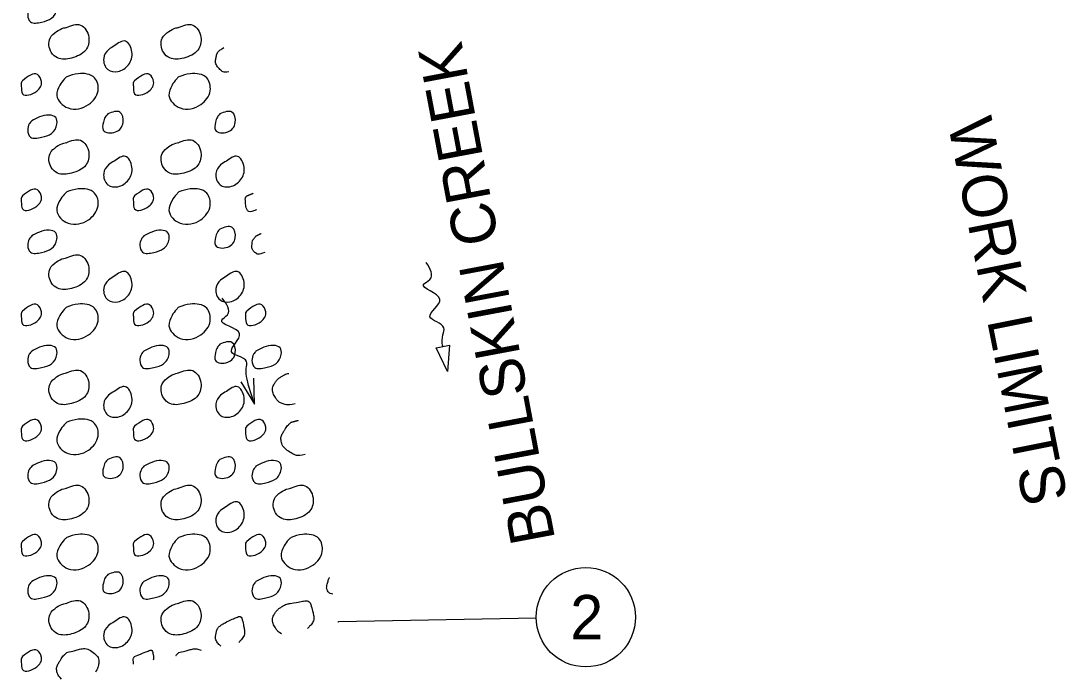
# Model space of a CAD drawing. Extents: x 0 to 340, y 0 to 220.
# Drawn here: x 150.51 to 183.47, y 110.25 to 131 of the extents above; entities that cross this region are included whole.
import ezdxf

# ---------------------------------------------------------------- set-up
doc = ezdxf.new("R2010")
doc.units = 0
for name, color, linetype in [('GE_P_Alignment_100_Stations', 7, 'Continuous'), ('MT_P_Temp_Road', 7, 'Continuous'), ('MT_P_Work_Area', 7, 'Continuous'), ('PF_P_Grade_Line', 7, 'Continuous'), ('SC_Scratch1', 7, 'Continuous'), ('TX_P_1', 7, 'Continuous')]:
    doc.layers.add(name, color=color, linetype=linetype)

msp = doc.modelspace()

# ---------------------------------------------------------------- linework, layer by layer
at = {"layer": 'GE_P_Alignment_100_Stations'}
msp.add_line((166.758, 112.174), (160.528, 112.053), dxfattribs=at)
at = {"layer": 'MT_P_Work_Area'}
msp.add_circle((168.325, 112.204), 1.567, dxfattribs=at)
at = {"layer": 'PF_P_Grade_Line'}
for p, q in [((157.884, 118.916), (157.856, 119.744)), ((157.446, 119.618), (157.884, 118.916))]:
    msp.add_line(p, q, dxfattribs=at)
msp.add_spline([(157.884, 118.916), (157.644, 119.711), (157.619, 120.048), (157.628, 120.268), (157.152, 120.566), (157.405, 121.151), (156.846, 121.565), (157.027, 121.739), (156.86, 122.263)], degree=3, dxfattribs=at)
at = {"layer": 'SC_Scratch1'}
for points in [[(150.855, 131.482), (151.105, 131.607), (151.405, 131.665), (151.616, 131.584), (151.65, 131.38), (151.48, 131.084), (151.166, 130.964), (150.815, 130.97), (150.729, 131.185), (150.78, 131.385), (150.855, 131.482)], [(151.941, 130.793), (152.395, 130.869), (152.655, 130.489), (152.558, 130.082), (152.112, 129.83), (151.672, 129.832), (151.473, 130.01), (151.436, 130.455), (151.641, 130.669), (151.867, 130.777), (151.95, 130.795)], [(155.477, 130.793), (155.931, 130.869), (156.19, 130.489), (156.094, 130.082), (155.648, 129.83), (155.208, 129.832), (155.009, 130.01), (154.972, 130.455), (155.177, 130.669), (155.403, 130.777), (155.485, 130.795)], [(153.457, 130.21), (153.809, 130.361), (154.016, 130.023), (153.905, 129.618), (153.571, 129.405), (153.26, 129.465), (153.127, 129.824), (153.273, 130.091), (153.457, 130.21)], [(150.563, 129.115), (151.038, 129.308), (151.164, 129.09), (151.015, 128.787), (150.565, 128.703), (150.525, 128.943), (150.53, 129.064), (150.563, 129.115)], [(151.962, 129.241), (152.318, 129.335), (152.839, 129.203), (152.946, 128.8), (152.65, 128.365), (152.002, 128.255), (151.648, 128.653), (151.743, 128.971), (151.881, 129.164), (151.962, 129.241)], [(154.099, 129.115), (154.574, 129.308), (154.699, 129.09), (154.55, 128.787), (154.1, 128.703), (154.061, 128.943), (154.065, 129.064), (154.099, 129.115)], [(155.498, 129.241), (155.854, 129.335), (156.374, 129.203), (156.482, 128.8), (156.186, 128.365), (155.538, 128.255), (155.184, 128.653), (155.279, 128.971), (155.417, 129.164), (155.498, 129.241)], [(150.855, 127.852), (151.105, 127.977), (151.405, 128.034), (151.616, 127.953), (151.65, 127.75), (151.48, 127.453), (151.166, 127.333), (150.815, 127.339), (150.729, 127.555), (150.78, 127.755), (150.855, 127.852)], [(153.253, 128.068), (153.635, 128.124), (153.739, 127.796), (153.499, 127.502), (153.112, 127.558), (153.115, 127.804), (153.173, 127.967), (153.253, 128.068)], [(156.789, 128.068), (157.17, 128.124), (157.274, 127.796), (157.034, 127.502), (156.648, 127.558), (156.65, 127.804), (156.709, 127.967), (156.789, 128.068)], [(151.941, 127.162), (152.395, 127.238), (152.655, 126.858), (152.558, 126.452), (152.112, 126.199), (151.672, 126.202), (151.473, 126.38), (151.436, 126.825), (151.641, 127.038), (151.867, 127.147), (151.95, 127.164)], [(155.477, 127.162), (155.931, 127.238), (156.19, 126.858), (156.094, 126.452), (155.648, 126.199), (155.208, 126.202), (155.009, 126.38), (154.972, 126.825), (155.177, 127.038), (155.403, 127.147), (155.485, 127.164)], [(153.457, 126.58), (153.809, 126.731), (154.016, 126.392), (153.905, 125.987), (153.571, 125.775), (153.26, 125.834), (153.127, 126.193), (153.273, 126.461), (153.457, 126.58)], [(156.993, 126.58), (157.344, 126.731), (157.552, 126.392), (157.44, 125.987), (157.107, 125.775), (156.796, 125.834), (156.663, 126.193), (156.809, 126.461), (156.993, 126.58)], [(150.563, 125.485), (151.038, 125.677), (151.164, 125.459), (151.015, 125.157), (150.565, 125.072), (150.525, 125.312), (150.53, 125.433), (150.563, 125.485)], [(151.962, 125.611), (152.318, 125.704), (152.839, 125.572), (152.946, 125.17), (152.65, 124.735), (152.002, 124.624), (151.648, 125.022), (151.743, 125.341), (151.881, 125.533), (151.962, 125.611)], [(154.099, 125.485), (154.574, 125.677), (154.699, 125.459), (154.55, 125.157), (154.1, 125.072), (154.061, 125.312), (154.065, 125.433), (154.099, 125.485)], [(155.498, 125.611), (155.854, 125.704), (156.374, 125.572), (156.482, 125.17), (156.186, 124.735), (155.538, 124.624), (155.184, 125.022), (155.279, 125.341), (155.417, 125.533), (155.498, 125.611)], [(150.855, 124.221), (151.105, 124.346), (151.405, 124.404), (151.616, 124.323), (151.65, 124.12), (151.48, 123.823), (151.166, 123.703), (150.815, 123.709), (150.729, 123.925), (150.78, 124.125), (150.855, 124.221)], [(154.39, 124.221), (154.64, 124.346), (154.941, 124.404), (155.152, 124.323), (155.186, 124.12), (155.015, 123.823), (154.702, 123.703), (154.35, 123.709), (154.264, 123.925), (154.316, 124.125), (154.39, 124.221)], [(156.789, 124.438), (157.17, 124.494), (157.274, 124.165), (157.034, 123.871), (156.648, 123.928), (156.65, 124.174), (156.709, 124.337), (156.789, 124.438)], [(151.941, 123.532), (152.395, 123.608), (152.655, 123.228), (152.558, 122.821), (152.112, 122.569), (151.672, 122.571), (151.473, 122.75), (151.436, 123.195), (151.641, 123.408), (151.867, 123.516), (151.95, 123.534)], [(153.457, 122.95), (153.809, 123.1), (154.016, 122.762), (153.905, 122.357), (153.571, 122.145), (153.26, 122.204), (153.127, 122.563), (153.273, 122.83), (153.457, 122.95)], [(156.993, 122.95), (157.344, 123.1), (157.552, 122.762), (157.44, 122.357), (157.107, 122.145), (156.796, 122.204), (156.663, 122.563), (156.809, 122.83), (156.993, 122.95)], [(150.563, 121.855), (151.038, 122.047), (151.164, 121.829), (151.015, 121.526), (150.565, 121.442), (150.525, 121.682), (150.53, 121.803), (150.563, 121.855)], [(151.962, 121.98), (152.318, 122.074), (152.839, 121.942), (152.946, 121.54), (152.65, 121.105), (152.002, 120.994), (151.648, 121.392), (151.743, 121.71), (151.881, 121.903), (151.962, 121.98)], [(154.099, 121.855), (154.574, 122.047), (154.699, 121.829), (154.55, 121.526), (154.1, 121.442), (154.061, 121.682), (154.065, 121.803), (154.099, 121.855)], [(155.498, 121.98), (155.854, 122.074), (156.374, 121.942), (156.482, 121.54), (156.186, 121.105), (155.538, 120.994), (155.184, 121.392), (155.279, 121.71), (155.417, 121.903), (155.498, 121.98)], [(157.634, 121.855), (158.109, 122.047), (158.235, 121.829), (158.086, 121.526), (157.636, 121.442), (157.597, 121.682), (157.601, 121.803), (157.634, 121.855)], [(150.855, 120.591), (151.105, 120.716), (151.405, 120.773), (151.616, 120.692), (151.65, 120.489), (151.48, 120.192), (151.166, 120.072), (150.815, 120.078), (150.729, 120.294), (150.78, 120.494), (150.855, 120.591)], [(154.39, 120.591), (154.64, 120.716), (154.941, 120.773), (155.152, 120.692), (155.186, 120.489), (155.015, 120.192), (154.702, 120.072), (154.35, 120.078), (154.264, 120.294), (154.316, 120.494), (154.39, 120.591)], [(156.789, 120.807), (157.17, 120.863), (157.274, 120.535), (157.034, 120.241), (156.648, 120.297), (156.65, 120.543), (156.709, 120.707), (156.789, 120.807)], [(157.926, 120.591), (158.176, 120.716), (158.477, 120.773), (158.688, 120.692), (158.722, 120.489), (158.551, 120.192), (158.238, 120.072), (157.886, 120.078), (157.8, 120.294), (157.852, 120.494), (157.926, 120.591)], [(151.941, 119.902), (152.395, 119.977), (152.655, 119.597), (152.558, 119.191), (152.112, 118.938), (151.672, 118.941), (151.473, 119.119), (151.436, 119.564), (151.641, 119.777), (151.867, 119.886), (151.95, 119.903)], [(155.477, 119.902), (155.931, 119.977), (156.19, 119.597), (156.094, 119.191), (155.648, 118.938), (155.208, 118.941), (155.009, 119.119), (154.972, 119.564), (155.177, 119.777), (155.403, 119.886), (155.485, 119.903)], [(153.457, 119.319), (153.809, 119.47), (154.016, 119.132), (153.905, 118.727), (153.571, 118.514), (153.26, 118.573), (153.127, 118.932), (153.273, 119.2), (153.457, 119.319)], [(156.993, 119.319), (157.344, 119.47), (157.552, 119.132), (157.44, 118.727), (157.107, 118.514), (156.796, 118.573), (156.663, 118.932), (156.809, 119.2), (156.993, 119.319)], [(150.563, 118.224), (151.038, 118.417), (151.164, 118.198), (151.015, 117.896), (150.565, 117.812), (150.525, 118.052), (150.53, 118.172), (150.563, 118.224)], [(151.962, 118.35), (152.318, 118.443), (152.839, 118.312), (152.946, 117.909), (152.65, 117.474), (152.002, 117.363), (151.648, 117.762), (151.743, 118.08), (151.881, 118.272), (151.962, 118.35)], [(154.099, 118.224), (154.574, 118.417), (154.699, 118.198), (154.55, 117.896), (154.1, 117.812), (154.061, 118.052), (154.065, 118.172), (154.099, 118.224)], [(157.634, 118.224), (158.109, 118.417), (158.235, 118.198), (158.086, 117.896), (157.636, 117.812), (157.597, 118.052), (157.601, 118.172), (157.634, 118.224)], [(150.855, 116.96), (151.105, 117.085), (151.405, 117.143), (151.616, 117.062), (151.65, 116.859), (151.48, 116.562), (151.166, 116.442), (150.815, 116.448), (150.729, 116.664), (150.78, 116.864), (150.855, 116.96)], [(153.253, 117.177), (153.635, 117.233), (153.739, 116.904), (153.499, 116.61), (153.112, 116.667), (153.115, 116.913), (153.173, 117.076), (153.253, 117.177)], [(154.39, 116.96), (154.64, 117.085), (154.941, 117.143), (155.152, 117.062), (155.186, 116.859), (155.015, 116.562), (154.702, 116.442), (154.35, 116.448), (154.264, 116.664), (154.316, 116.864), (154.39, 116.96)], [(156.789, 117.177), (157.17, 117.233), (157.274, 116.904), (157.034, 116.61), (156.648, 116.667), (156.65, 116.913), (156.709, 117.076), (156.789, 117.177)], [(157.926, 116.96), (158.176, 117.085), (158.477, 117.143), (158.688, 117.062), (158.722, 116.859), (158.551, 116.562), (158.238, 116.442), (157.886, 116.448), (157.8, 116.664), (157.852, 116.864), (157.926, 116.96)], [(151.941, 116.271), (152.395, 116.347), (152.655, 115.967), (152.558, 115.56), (152.112, 115.308), (151.672, 115.31), (151.473, 115.489), (151.436, 115.934), (151.641, 116.147), (151.867, 116.255), (151.95, 116.273)], [(155.477, 116.271), (155.931, 116.347), (156.19, 115.967), (156.094, 115.56), (155.648, 115.308), (155.208, 115.31), (155.009, 115.489), (154.972, 115.934), (155.177, 116.147), (155.403, 116.255), (155.485, 116.273)], [(159.013, 116.271), (159.467, 116.347), (159.726, 115.967), (159.629, 115.56), (159.184, 115.308), (158.744, 115.31), (158.544, 115.489), (158.508, 115.934), (158.713, 116.147), (158.939, 116.255), (159.021, 116.273)], [(156.993, 115.689), (157.344, 115.839), (157.552, 115.501), (157.44, 115.096), (157.107, 114.884), (156.796, 114.943), (156.663, 115.302), (156.809, 115.569), (156.993, 115.689)], [(150.563, 114.594), (151.038, 114.786), (151.164, 114.568), (151.015, 114.265), (150.565, 114.181), (150.525, 114.421), (150.53, 114.542), (150.563, 114.594)], [(151.962, 114.719), (152.318, 114.813), (152.839, 114.681), (152.946, 114.279), (152.65, 113.844), (152.002, 113.733), (151.648, 114.131), (151.743, 114.449), (151.881, 114.642), (151.962, 114.719)], [(154.099, 114.594), (154.574, 114.786), (154.699, 114.568), (154.55, 114.265), (154.1, 114.181), (154.061, 114.421), (154.065, 114.542), (154.099, 114.594)], [(155.498, 114.719), (155.854, 114.813), (156.374, 114.681), (156.482, 114.279), (156.186, 113.844), (155.538, 113.733), (155.184, 114.131), (155.279, 114.449), (155.417, 114.642), (155.498, 114.719)], [(157.634, 114.594), (158.109, 114.786), (158.235, 114.568), (158.086, 114.265), (157.636, 114.181), (157.597, 114.421), (157.601, 114.542), (157.634, 114.594)], [(159.034, 114.719), (159.389, 114.813), (159.91, 114.681), (160.018, 114.279), (159.722, 113.844), (159.074, 113.733), (158.719, 114.131), (158.814, 114.449), (158.953, 114.642), (159.034, 114.719)], [(150.855, 113.33), (151.105, 113.455), (151.405, 113.512), (151.616, 113.431), (151.65, 113.228), (151.48, 112.931), (151.166, 112.811), (150.815, 112.817), (150.729, 113.033), (150.78, 113.233), (150.855, 113.33)], [(153.253, 113.546), (153.635, 113.602), (153.739, 113.274), (153.499, 112.98), (153.112, 113.036), (153.115, 113.282), (153.173, 113.446), (153.253, 113.546)], [(154.39, 113.33), (154.64, 113.455), (154.941, 113.512), (155.152, 113.431), (155.186, 113.228), (155.015, 112.931), (154.702, 112.811), (154.35, 112.817), (154.264, 113.033), (154.316, 113.233), (154.39, 113.33)], [(157.926, 113.33), (158.176, 113.455), (158.477, 113.512), (158.688, 113.431), (158.722, 113.228), (158.551, 112.931), (158.238, 112.811), (157.886, 112.817), (157.8, 113.033), (157.852, 113.233), (157.926, 113.33)], [(151.941, 112.641), (152.395, 112.716), (152.655, 112.336), (152.558, 111.93), (152.112, 111.677), (151.672, 111.68), (151.473, 111.858), (151.436, 112.303), (151.641, 112.516), (151.867, 112.625), (151.95, 112.642)], [(155.477, 112.641), (155.931, 112.716), (156.19, 112.336), (156.094, 111.93), (155.648, 111.677), (155.208, 111.68), (155.009, 111.858), (154.972, 112.303), (155.177, 112.516), (155.403, 112.625), (155.485, 112.642)], [(153.457, 112.058), (153.809, 112.209), (154.016, 111.871), (153.905, 111.466), (153.571, 111.253), (153.26, 111.312), (153.127, 111.671), (153.273, 111.939), (153.457, 112.058)], [(150.563, 110.963), (151.038, 111.156), (151.164, 110.937), (151.015, 110.635), (150.565, 110.551), (150.525, 110.791), (150.53, 110.911), (150.563, 110.963)]]:
    msp.add_spline(points, degree=3, dxfattribs=at)
for points, degree in [([(157.07, 129.396), (156.981, 129.377), (156.878, 129.383), (156.796, 129.465), (156.682, 129.577), (156.64, 129.709), (156.663, 129.824), (156.681, 129.915), (156.723, 130.035), (156.809, 130.091), (156.845, 130.115), (156.881, 130.139), (156.917, 130.162)], 3), ([(157.634, 125.485), (157.701, 125.512), (157.767, 125.539), (157.834, 125.567)], 2), ([(157.938, 125.045), (157.816, 124.985), (157.675, 124.973), (157.636, 125.072), (157.605, 125.151), (157.6, 125.232), (157.597, 125.312), (157.595, 125.353), (157.58, 125.397), (157.601, 125.433), (157.612, 125.452), (157.624, 125.468), (157.634, 125.485)], 3), ([(157.926, 124.221), (157.979, 124.248), (158.033, 124.275), (158.086, 124.301)], 2), ([(158.207, 123.695), (158.102, 123.666), (157.986, 123.619), (157.886, 123.709), (157.813, 123.774), (157.798, 123.85), (157.8, 123.925), (157.802, 123.991), (157.81, 124.069), (157.852, 124.125), (157.877, 124.157), (157.901, 124.189), (157.926, 124.221)], 3), ([(159.157, 118.931), (159.022, 118.895), (158.875, 118.885), (158.744, 118.941), (158.658, 118.977), (158.596, 119.039), (158.544, 119.119), (158.458, 119.253), (158.432, 119.438), (158.508, 119.564), (158.558, 119.648), (158.626, 119.722), (158.713, 119.777), (158.787, 119.824), (158.857, 119.868), (158.939, 119.886), (158.947, 119.888), (158.956, 119.889), (158.965, 119.891)], 3), ([(159.475, 117.334), (159.337, 117.289), (159.192, 117.293), (159.074, 117.363), (158.916, 117.456), (158.75, 117.596), (158.719, 117.762), (158.701, 117.864), (158.754, 117.984), (158.814, 118.08), (158.858, 118.148), (158.896, 118.217), (158.953, 118.272), (158.98, 118.298), (159.007, 118.324), (159.034, 118.35)], 3), ([(159.034, 118.35), (159.109, 118.37), (159.185, 118.39), (159.261, 118.41)], 2), ([(160.352, 112.933), (160.28, 112.943), (160.213, 112.977), (160.184, 113.036), (160.145, 113.114), (160.165, 113.204), (160.186, 113.282), (160.201, 113.337), (160.209, 113.4), (160.244, 113.446), (160.246, 113.447), (160.248, 113.449), (160.249, 113.451)], 3), ([(159.013, 112.641), (159.164, 112.666), (159.316, 112.695), (159.467, 112.716), (159.618, 112.737), (159.688, 112.478), (159.726, 112.336), (159.761, 112.208), (159.738, 112.05), (159.629, 111.93), (159.602, 111.9), (159.575, 111.874), (159.546, 111.85)], 3), ([(158.736, 111.683), (158.654, 111.72), (158.595, 111.78), (158.544, 111.858), (158.458, 111.992), (158.432, 112.177), (158.508, 112.303), (158.558, 112.387), (158.626, 112.461), (158.713, 112.516), (158.787, 112.563), (158.857, 112.607), (158.939, 112.625), (158.966, 112.631), (158.994, 112.636), (159.021, 112.642)], 3), ([(156.823, 111.289), (156.814, 111.296), (156.805, 111.304), (156.796, 111.312), (156.682, 111.425), (156.64, 111.557), (156.663, 111.671), (156.681, 111.762), (156.723, 111.882), (156.809, 111.939), (156.87, 111.98), (156.932, 112.018), (156.993, 112.058)], 3), ([(156.993, 112.058), (157.11, 112.108), (157.227, 112.159), (157.344, 112.209), (157.466, 112.261), (157.525, 111.994), (157.552, 111.871), (157.58, 111.74), (157.546, 111.593), (157.44, 111.466), (157.421, 111.443), (157.402, 111.423), (157.382, 111.404)], 3), ([(160.517, 112.05), (160.52, 112.053), (160.524, 112.055), (160.527, 112.057)], 2), ([(151.799, 110.253), (151.723, 110.325), (151.665, 110.409), (151.648, 110.501), (151.629, 110.603), (151.682, 110.723), (151.743, 110.819), (151.786, 110.887), (151.824, 110.956), (151.881, 111.011), (151.908, 111.037), (151.935, 111.063), (151.962, 111.089)], 3), ([(151.962, 111.089), (152.081, 111.121), (152.199, 111.151), (152.318, 111.182), (152.491, 111.227), (152.665, 111.195), (152.839, 111.051), (152.973, 110.938), (152.982, 110.772), (152.946, 110.648), (152.929, 110.589), (152.904, 110.531), (152.872, 110.474)], 3), ([(154.099, 110.963), (154.257, 111.027), (154.415, 111.095), (154.574, 111.156), (154.652, 111.185), (154.692, 111.012), (154.699, 110.937), (154.702, 110.908), (154.698, 110.878), (154.688, 110.849)], 3), ([(155.402, 110.996), (155.407, 111.001), (155.412, 111.006), (155.417, 111.011), (155.444, 111.037), (155.471, 111.063), (155.498, 111.089)], 3), ([(155.498, 111.089), (155.616, 111.121), (155.735, 111.151), (155.854, 111.182), (155.968, 111.212), (156.083, 111.208), (156.198, 111.16)], 3), ([(154.065, 110.72), (154.063, 110.744), (154.062, 110.767), (154.061, 110.791), (154.06, 110.831), (154.044, 110.875), (154.065, 110.911), (154.076, 110.93), (154.088, 110.946), (154.099, 110.963)], 3)]:
    msp.add_open_spline(points, degree=degree, dxfattribs=at)
at = {"layer": 'TX_P_1'}
for p, q in [((163.605, 120.699), (164.026, 120.781)), ((163.968, 119.954), (163.605, 120.699)), ((164.026, 120.781), (163.968, 119.954))]:
    msp.add_line(p, q, dxfattribs=at)
msp.add_spline([(163.817, 120.739), (163.811, 120.77), (163.822, 121.108), (163.853, 121.326), (163.411, 121.672), (163.723, 122.227), (163.21, 122.697), (163.408, 122.852), (163.297, 123.389)], degree=3, dxfattribs=at)

# ---------------------------------------------------------------- texts
at = {"layer": 'MT_P_Temp_Road'}
msp.add_text('BULLSKIN CREEK', height=1.4, rotation=100.671, dxfattribs=at).set_placement((167.364, 114.653))
at = {"layer": 'MT_P_Work_Area'}
msp.add_text('WORK LIMITS', height=1.4, rotation=281.2824, dxfattribs=at).set_placement((179.73, 127.789))
msp.add_text('2', height=1.4, dxfattribs=at).set_placement((167.833, 111.504))

doc.saveas('drawing.dxf')
